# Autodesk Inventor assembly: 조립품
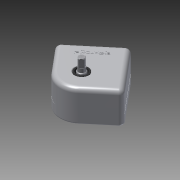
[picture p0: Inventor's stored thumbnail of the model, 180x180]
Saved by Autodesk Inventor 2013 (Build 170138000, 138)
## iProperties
Created: 2015-11
Part Number: 조립품
Document SubType Name: Assembly
Designer: Administrator
Author: Administrator
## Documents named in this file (13)
- C:\Documents and Settings\Administrator\바탕 화면\양진이\2급\박인욱\조립품.iam
- C:\Documents and Settings\Administrator\바탕 화면\양진이\2급\박인욱\베어링 6002.ipt
- C:\Documents and Settings\Administrator\바탕 화면\양진이\2급\박인욱\로드 축.ipt
- C:\Documents and Settings\Administrator\바탕 화면\양진이\2급\박인욱\편심 축.ipt
- C:\Documents and Settings\Administrator\바탕 화면\양진이\2급\박인욱\앞커버.ipt
- C:\Documents and Settings\Administrator\바탕 화면\양진이\2급\박인욱\베어링 6001.ipt
- C:\Documents and Settings\Administrator\바탕 화면\양진이\2급\박인욱\오일실 12 x 22.ipt
- C:\Documents and Settings\Administrator\바탕 화면\양진이\2급\박인욱\축 커버.ipt
- C:\Documents and Settings\Administrator\바탕 화면\양진이\2급\박인욱\2급본체.ipt
- C:\Documents and Settings\Administrator\바탕 화면\양진이\2급\박인욱\로드.ipt
- C:\Documents and Settings\Administrator\바탕 화면\양진이\2급\박인욱\오일실 15 x 25.ipt
- C:\Documents and Settings\Administrator\바탕 화면\양진이\2급\박인욱\M3 x 0.5.ipt
- C:\Documents and Settings\Administrator\바탕 화면\양진이\2급\박인욱\M4 x 0.7.ipt
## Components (10 placed, 3 different names)
1. 2급본체:1
2. M4 x 0.7:1
3. M4 x 0.7:2
4. M4 x 0.7:3
5. M4 x 0.7:4
6. M4 x 0.7:5
7. M3 x 0.5:1
8. M3 x 0.5:2
9. M3 x 0.5:3
10. M3 x 0.5:4
